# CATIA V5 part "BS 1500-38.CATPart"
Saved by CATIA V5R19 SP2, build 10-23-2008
Part number: BS 1500-38
Bounding box of the stored display mesh (mm): x -31.459 to 31.459, y -31.459 to 31.459, z 0 to 120
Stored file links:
  C:\Users\Bora\Desktop\3D Katı model\BS serisi\BS 1500\BS 1500-38.CATPart
  C:\Program Files\Dassault Systemes\B19\intel_a\reffiles\standard\MetricThickPitch.txt
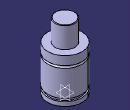
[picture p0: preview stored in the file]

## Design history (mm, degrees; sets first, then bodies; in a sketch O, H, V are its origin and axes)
Body1 (main body)
  Sketch1 on yz-plane, origin (0, 0, 0), H (0, 1, 0), V (0, 0, 1)
    point P1 (31.5, 65)
    point P2 (31.5, 61)
    point P3 (31.5, 65)
    point P7 (18, 119)
    point P9 (18, 119)
    point P14 (31.5, 61)
    arc A1 centre (31.5, 63) radius 2 from (31.5, 65) to (31.5, 61) ccw
    line L1 (31.5, 65) -> (31.5, 81)
    line L2 (31.5, 0) -> (31.5, 8)
    arc A2 centre (17, 119) radius 1 from (18, 119) to (17, 120) ccw
    line L3 (18, 119) -> (18, 81)
    line L4 (29, 13) -> (29, 8)
    line L5 (31.5, 13) -> (31.5, 61)
    line L6 (17, 120) -> (0, 120)
    point P15 (0, 120)
    line L7 (18, 81) -> (31.5, 81)
    line L8 (0, 0) -> (31.5, 0)
    line L9 (29, 13) -> (31.5, 13)
    line L10 (29, 8) -> (31.5, 8)
    coincidence: P15 V, P1 P3, P2 P14, P7 P9
    tangency: L6 A2
    horizontal: L7 H, L8 H, L9 H, L10 H
  Shaft1: profile Sketch1, axis Sketch1.V, angle 360
  Sketch2 on face of Shaft1 from Sketch1.L8, origin (0, 0, 0), H (1, 0, 0), V (0, -1, 0)
    point P1 (10, 0)
    distance P1 V = 10
  Hole1: placed by Sketch2, at (10, 0, 0) direction (0, 0, 1), diameter 6.647, depth 5, threaded "M8", thread diameter 8, thread depth 5, pitch 1.25
  CircPattern1: of Hole1, instances 2, angular step 180, axis from xy-plane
